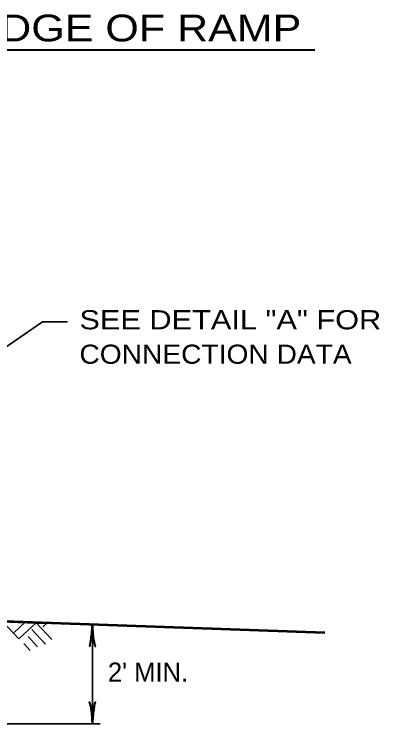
# Model space of a CAD drawing. Extents: x -54 to 626, y -41 to 399.
# Drawn here: x 119.6 to 167.3, y 98.6 to 191.3 of the extents above; entities that cross this region are included whole.
import ezdxf
from ezdxf.enums import TextEntityAlignment as Align

# ---------------------------------------------------------------- set-up
doc = ezdxf.new("R2010")
doc.units = 0
doc.header["$LTSCALE"] = 0.9
doc.layers.add('1', color=7, linetype='Continuous', lineweight=35)

msp = doc.modelspace()

# ---------------------------------------------------------------- linework, layer by layer
at = {"layer": '1', "lineweight": 40}
msp.add_line((42.2643, 186.5966), (158.8272, 186.5966), dxfattribs=at)
at = {"layer": '1', "lineweight": 53}
msp.add_line((115.4317, 112.0762), (160.1525, 110.5146), dxfattribs=at)
at = {"layer": '1'}
for p, q in [((118.0687, 111.9441), (120.1906, 109.6686)), ((121.0268, 111.8407), (119.5995, 110.5097)), ((122.446, 111.7912), (120.1906, 109.6686)), ((122.446, 111.7912), (124.51, 109.5778)), ((123.8652, 111.7417), (123.3273, 111.2401)), ((129.8067, 98.5938), (129.8067, 111.5393)), ((121.8949, 110.9099), (123.6696, 109.0068)), ((121.4017, 109.9665), (122.6362, 108.6427)), ((120.8499, 109.0652), (121.6793, 108.1757)), ((115.8067, 98.5938), (130.8067, 98.5938))]:
    msp.add_line(p, q, dxfattribs=at)
msp.add_lwpolyline([(116.4862, 146.4421), (123.2822, 151.0822), (126.5517, 151.0822)], dxfattribs=at)
at = {"layer": '1', "lineweight": 53}
msp.add_lwpolyline([(98.1902, 112.6782), (115.4317, 112.0762), (123.6242, 111.7901)], dxfattribs=at)
at = {"layer": '1', "lineweight": 40}
for centre, major_axis, ratio, start_param, end_param in [((129.5951, 110.4188), (0.1757, 1.7565), 0.07063, 3.1407148, 5.41811), ((129.5951, 110.4188), (0.1757, 1.7565), 0.07063, 3.1407148, 5.41811), ((130.083, 110.4481), (-0.1562, 1.7857), 0.122415, 0.8963533, 3.1415927), ((130.083, 110.4481), (-0.1562, 1.7857), 0.122415, 0.8963533, 3.1415927), ((129.5304, 99.685), (0.1562, -1.7857), 0.122415, 0.8963533, 3.1415927), ((130.0183, 99.7143), (-0.1757, -1.7565), 0.07063, 3.1407148, 5.41811)]:
    msp.add_ellipse(centre, major_axis=major_axis, ratio=ratio, start_param=start_param, end_param=end_param, dxfattribs=at)

# ---------------------------------------------------------------- texts
at = {"layer": '1', "width": 1.2}
msp.add_text('TYPICAL SECTION - LEFT EDGE OF RAMP', height=3.5, dxfattribs=at).set_placement((100.4449, 187.7051), align=Align.CENTER)
at = {"layer": '1'}
for s, width, p in [('SEE DETAIL "A" FOR', 1.2, (128.1103, 150.1043)), ('CONNECTION DATA', 1.1, (128.1103, 145.6043))]:
    msp.add_text(s, height=2.5, dxfattribs=dict(at, width=width)).set_placement(p)
msp.add_text("2' MIN.", height=2.5, dxfattribs=at).set_placement((131.8285, 104.0857))

doc.saveas('drawing.dxf')
